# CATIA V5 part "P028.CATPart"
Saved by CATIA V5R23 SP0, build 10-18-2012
Part number: 05-LICP-T02-E-S05-P028
Definition: Rondelle Plate
Description: Rondelle Plate
Bounding box of the stored display mesh (mm): x -2 to 0, y -10.992 to 10.992, z -10.984 to 10.984
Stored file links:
  C:\wamp\www\COURS\CONCEPTION GMP1\TITRE 02-SEMESTRE 2\03-TP7-PRESSE MECANIQUE\eleve\P028.CATPart
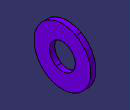
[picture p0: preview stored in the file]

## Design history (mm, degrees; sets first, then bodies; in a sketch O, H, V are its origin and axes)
Body1 (main body)
  Sketch1 on zx-plane, origin (0, 0, 0), H (-1, 0, 0), V (0, 0, 1)
    point P1 (0, 11)
    line L1 (0, 11) -> (2, 11)
    line L2 (2, 11) -> (2, 5)
    line L3 (2, 5) -> (0, 5)
    line L4 (0, 5) -> (0, 11)
    distance L3 H = 5
    length L2 = 6
    length L1 = 2
    coincidence: P1 V
    horizontal: L1 H, L3 H
    vertical: L2 V, L4 V
  Shaft1: profile Sketch1, axis Sketch1.H, angle 360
